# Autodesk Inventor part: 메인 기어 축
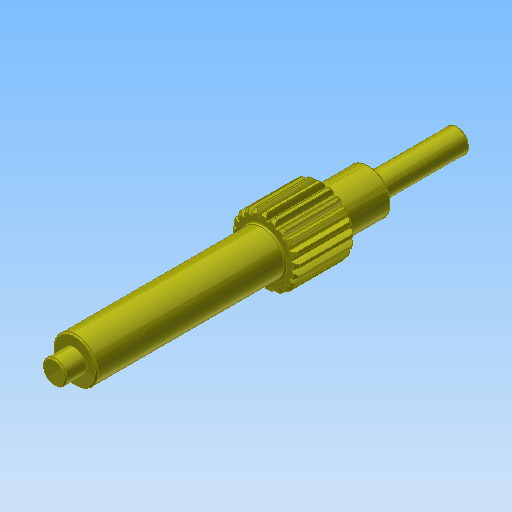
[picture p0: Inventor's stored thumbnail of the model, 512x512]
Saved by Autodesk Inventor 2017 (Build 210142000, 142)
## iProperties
Created: 2018-12
Part Number: 메인 기어 축
Material: 강철, 연강
Document SubType Name: Modeling
Designer: mduedu
Categories: <?xml version="1.0" encoding="UTF-16"?> <MemberInstance><Categories><FamilyTemplate><FamilyTemplateParameter ValueType="xs:double" Id="1" ObjectReferenceKey="da
Density: 1 g/cm^3
Appearance: 노란색
CustomPartVersion: 1
Author: mduedu
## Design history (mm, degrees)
sketch "Sketch1"
  geometry: C1 r 11.3 at (0, 0)
  constraints: 1 centre point
  dimensions: "d0" = 22.6 diameter of C1 (= da_da)
extrude "Extrusion1" new body sketch "Sketch1" distance "d1" = 20 (= da_b); taper "d2" = 0 deg
workplane "Work Plane2"
sketch "Sketch2"
  geometry: C1 r 11.3 at (0, 0) reference; C2 r 10.5 at (0, 0)
  constraints: 1 centre point, 1 coincident
  dimensions: "d3" = 21 diameter of C2 (= da_dw)
feature "피치 지름" sketch "Sketch2" dims "d4" = 10, "d5" = 0
workplane "Work Plane8"
workplane "Work Plane9"
chamfer "모따기1" distance "d49" = 1; stored, may be unused: second distance "d50" = 2, angle "d51" = 45 deg
sketch "스케치3"
  geometry: C1 r 7.5 at (0, 0); 1 further point
  constraints: 1 centre point, 1 coincident
  dimensions: "d52" = 15 diameter of C1
extrude "돌출2" join sketch "스케치3" distance "d53" = 64; taper "d54" = 0 deg
sketch "스케치4"
  geometry: C1 r 4 at (0, 0); 1 further point
  constraints: 1 centre point, 1 coincident
  dimensions: "d55" = 8 diameter of C1
extrude "돌출3" join sketch "스케치4" distance "d56" = 7; taper "d57" = 0 deg
sketch "스케치5"
  geometry: C1 r 7.5 at (0, 0) reference; C2 r 7.5 at (0, 0) reference; 1 further point
extrude "돌출4" join sketch "스케치5" distance "d58" = 16; taper "d59" = 0 deg
sketch "스케치6"
  geometry: C1 r 4 at (0, 0); 1 further point
  constraints: 1 centre point, 1 coincident
  dimensions: "d60" = 8 diameter of C1
extrude "돌출5" join sketch "스케치6" distance "d61" = 30; taper "d62" = 0 deg
chamfer "모따기2" distance "d63" = 0.5; stored, may be unused: second distance "d64" = 2, angle "d65" = 45 deg
fillet "모깎기1" dims "d66" = 0.5
feature "스퍼 기어" dims "d39" = 0, "da_b" = 20, "da_d" = 21, "da_aw" = 31, "da_da" = 22.6, "da_df" = 19.086, "da_dw" = 21, angle "da_beta" = 0 deg, "da_lefttooth" = 0, "da_righttooth" = 0
sketch "스케치7" dims "d67" = 18
  geometry: C1 r 0.25 at (0, -9); 2 further points
  constraints: 2 vertical alignment, 1 centre point, 1 coincident, 2 other
  dimensions: "d68" = 0.5 diameter of C1
extrude "돌출6" join sketch "스케치7" distance "d69" = 0.3; taper "d70" = 0 deg
body "Solid1"
body "Srf1"
node "투영된 루프1"
other parameters: "d16" = 31 (= da_aw), "d17" = 0, "d34" = 1.496 (computed from da_z), "d41" = 0, "d43" = 31 (= da_aw), "d46" = 31 (= da_aw), "d47" = 0, "d48" = 0
